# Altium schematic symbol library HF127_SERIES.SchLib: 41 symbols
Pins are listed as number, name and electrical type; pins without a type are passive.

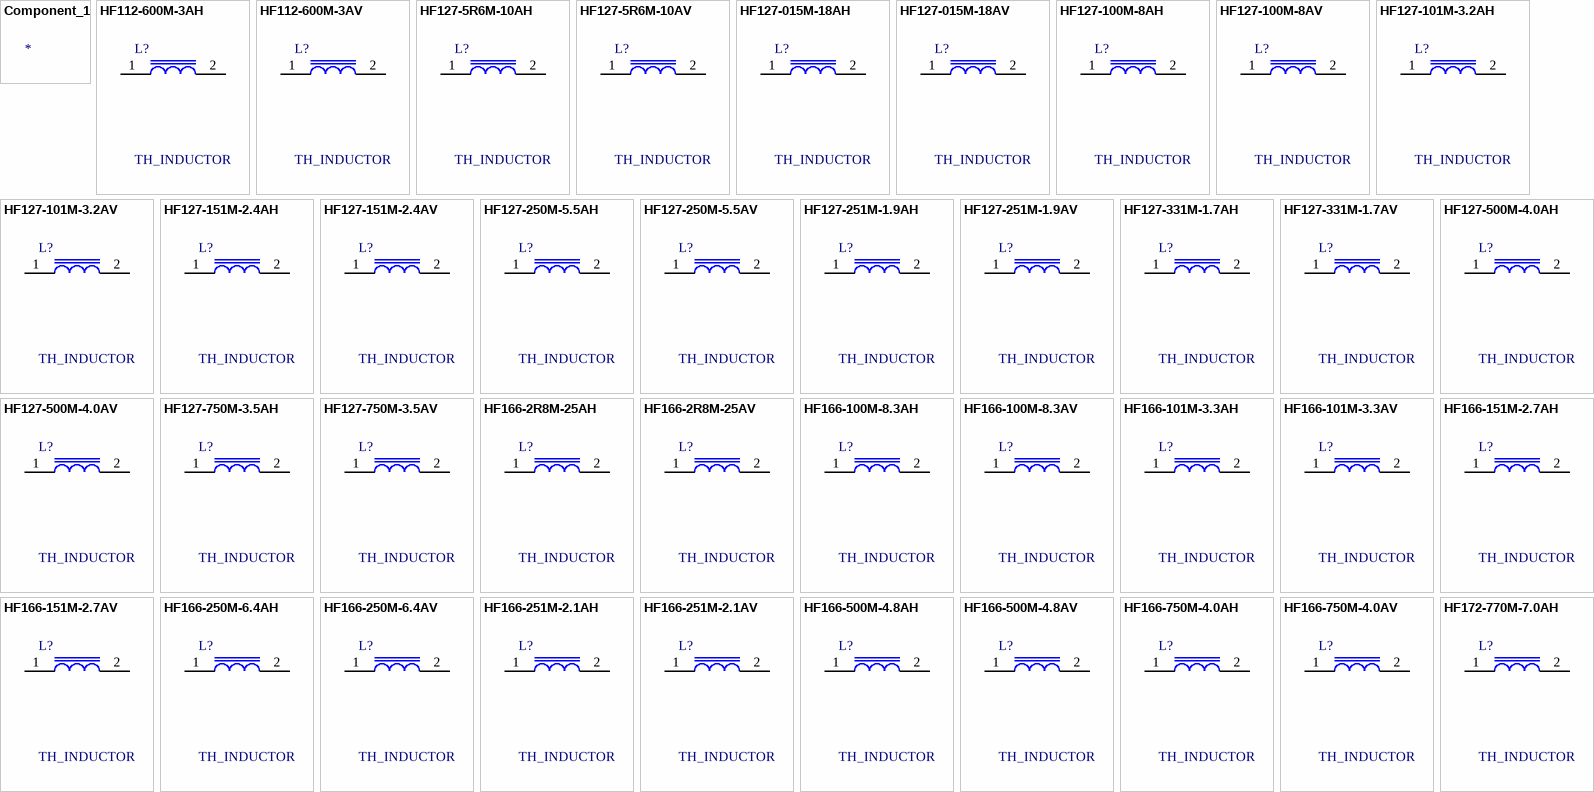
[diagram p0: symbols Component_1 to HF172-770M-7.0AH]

## Component_1
designator *  (value not drawn)

## HF112-600M-3AH
designator L?, comment TH_INDUCTOR
POWER INDUCTOR 3 A, 60 uH, 30 mOhms, OD 13.46 mm, HT 7.62 mm; Manufacturer #1: CWS; Sim.Analog.Prefix: L; Sim.Analog.Order: Model$; Current: 3.0 A; Inductance: 60.00 uH
footprint HF112-600M-3AH
pins: 1, 2

## HF112-600M-3AV
designator L?, comment TH_INDUCTOR
POWER INDUCTOR 3 A, 60 uH, 30 mOhms, OD 13.46 mm, HT 7.62 mm; Manufacturer #1: CWS; Sim.Analog.Prefix: L; Sim.Analog.Order: Model$; Current: 3.0 A; Inductance: 60.00 uH
footprint HF112-600M-3AV
pins: 1, 2

## HF127-5R6M-10AH
designator L?, comment TH_INDUCTOR
POWER INDUCTOR 10 A, 5.6 uH, 4 mOhms, OD 18.49 mm, HT 9.4 mm; Manufacturer #1: CWS; Sim.Analog.Prefix: L; Sim.Analog.Order: Model$; Current: 10.0 A; DCR: 4 mOhms; Inductance: 5.60 uH
footprint HF127-5R6M-10AH
pins: 1, 2

## HF127-5R6M-10AV
designator L?, comment TH_INDUCTOR
POWER INDUCTOR 10 A, 5.6 uH, 4 mOhms, OD 18.49 mm, HT 9.4 mm; Manufacturer #1: CWS; Sim.Analog.Prefix: L; Sim.Analog.Order: Model$; Current: 10.0 A; DCR: 4 mOhms; Inductance: 5.60 uH
footprint HF127-5R6M-10AV
pins: 1, 2

## HF127-015M-18AH
designator L?, comment TH_INDUCTOR
POWER INDUCTOR 18 A, 1.5 uH, 2 mOhms, OD 18.8 mm, HT 9.65 mm; Manufacturer #1: CWS; Sim.Analog.Prefix: L; Sim.Analog.Order: Model$; OD: 18.8 mm; Current: 18.0 A; DCR: 2 mOhms; Inductance: 1.50 uH
footprint HF127-015M-18AH
pins: 1, 2

## HF127-015M-18AV
designator L?, comment TH_INDUCTOR
POWER INDUCTOR 18 A, 1.5 uH, 2 mOhms, OD 18.8 mm, HT 9.65 mm; Manufacturer #1: CWS; Sim.Analog.Prefix: L; Sim.Analog.Order: Model$; OD: 18.8 mm; Current: 18.0 A; DCR: 2 mOhms; Inductance: 1.50 uH
footprint HF127-015M-18AV
pins: 1, 2

## HF127-100M-8AH
designator L?, comment TH_INDUCTOR
POWER INDUCTOR 8 A, 10 uH, 10 mOhms, OD 15.88 mm, HT 7.62 mm; Manufacturer #1: CWS; Sim.Analog.Prefix: L; Sim.Analog.Order: Model$; Current: 8.0 A; Inductance: 10.00 uH
footprint HF127-100M-8AH
pins: 1, 2

## HF127-100M-8AV
designator L?, comment TH_INDUCTOR
POWER INDUCTOR 8 A, 10 uH, 10 mOhms, OD 15.88 mm, HT 7.62 mm; Manufacturer #1: CWS; Sim.Analog.Prefix: L; Sim.Analog.Order: Model$; Current: 8.0 A; Inductance: 10.00 uH
footprint HF127-100M-8AV
pins: 1, 2

## HF127-101M-3.2AH
designator L?, comment TH_INDUCTOR
POWER INDUCTOR 3.2 A, 100 uH, 55 mOhms, OD 15.88 mm, HT 7.62 mm; Manufacturer #1: CWS; Sim.Analog.Prefix: L; Sim.Analog.Order: Model$; Current: 3.2 A; Inductance: 100.00 uH
footprint HF127-101M-3.2AV
pins: 1, 2

## HF127-101M-3.2AV
designator L?, comment TH_INDUCTOR
POWER INDUCTOR 3.2 A, 100 uH, 55 mOhms, OD 15.88 mm, HT 7.62 mm; Manufacturer #1: CWS; Sim.Analog.Prefix: L; Sim.Analog.Order: Model$; Current: 3.2 A; Inductance: 100.00 uH
footprint HF127-101M-3.2AV
pins: 1, 2

## HF127-151M-2.4AH
designator L?, comment TH_INDUCTOR
POWER INDUCTOR 2.4 A, 150 uH, 100 mOhms, OD 15.88 mm, HT 7.62 mm; Manufacturer #1: CWS; Sim.Analog.Prefix: L; Sim.Analog.Order: Model$; Current: 2.4 A; Inductance: 150.00 uH
footprint HF127-151M-2.4AH 
pins: 1, 2

## HF127-151M-2.4AV
designator L?, comment TH_INDUCTOR
POWER INDUCTOR 2.4 A, 150 uH, 100 mOhms, OD 15.88 mm, HT 7.62 mm; Manufacturer #1: CWS; Sim.Analog.Prefix: L; Sim.Analog.Order: Model$; Current: 2.4 A; Inductance: 150.00 uH
footprint HF127-151M-2.4AV
pins: 1, 2

## HF127-250M-5.5AH
designator L?, comment TH_INDUCTOR
POWER INDUCTOR 5.5 A, 25 uH, 20 mOhms, OD 15.88 mm, HT 7.62 mm; Manufacturer #1: CWS; Sim.Analog.Prefix: L; Sim.Analog.Order: Model$; Current: 5.5 A; Inductance: 25.00 uH
footprint HF127-250M-5.5AH
pins: 1, 2

## HF127-250M-5.5AV
designator L?, comment TH_INDUCTOR
POWER INDUCTOR 5.5 A, 25 uH, 20 mOhms, OD 15.88 mm, HT 7.62 mm; Manufacturer #1: CWS; Sim.Analog.Prefix: L; Sim.Analog.Order: Model$; Current: 5.5 A; Inductance: 25.00 uH
footprint HF127-250M-5.5AV
pins: 1, 2

## HF127-251M-1.9AH
designator L?, comment TH_INDUCTOR
POWER INDUCTOR 1.9 A, 250 uH, 160 mOhms, OD 15.88 mm, HT 7.62 mm; Manufacturer #1: CWS; Sim.Analog.Prefix: L; Sim.Analog.Order: Model$; Current: 1.9 A; Inductance: 250.00 uH
footprint HF127-251M-1.9AH 
pins: 1, 2

## HF127-251M-1.9AV
designator L?, comment TH_INDUCTOR
POWER INDUCTOR 1.9 A, 250 uH, 160 mOhms, OD 15.88 mm, HT 7.62 mm; Manufacturer #1: CWS; Sim.Analog.Prefix: L; Sim.Analog.Order: Model$; Current: 1.9 A; Inductance: 250.00 uH
footprint HF127-251M-1.9AV
pins: 1, 2

## HF127-331M-1.7AH
designator L?, comment TH_INDUCTOR
POWER INDUCTOR 1.7 A, 330 uH, 190 mOhms, OD 15.88 mm, HT 7.62 mm; Manufacturer #1: CWS; Sim.Analog.Prefix: L; Sim.Analog.Order: Model$; Current: 1.7 A; Inductance: 330.00 uH
footprint HF127-331M-1.7AH
pins: 1, 2

## HF127-331M-1.7AV
designator L?, comment TH_INDUCTOR
POWER INDUCTOR 1.7 A, 330 uH, 190 mOhms, OD 15.88 mm, HT 7.62 mm; Manufacturer #1: CWS; Sim.Analog.Prefix: L; Sim.Analog.Order: Model$; Current: 1.7 A; Inductance: 330.00 uH
footprint HF127-331M-1.7AV
pins: 1, 2

## HF127-500M-4.0AH
designator L?, comment TH_INDUCTOR
POWER INDUCTOR 4 A, 50 uH, 35 mOhms, OD 15.88 mm, HT 7.62 mm; Manufacturer #1: CWS; Sim.Analog.Prefix: L; Sim.Analog.Order: Model$; Current: 4.0 A; Inductance: 50.00 uH
footprint HF127-500M-4.0AH
pins: 1, 2

## HF127-500M-4.0AV
designator L?, comment TH_INDUCTOR
POWER INDUCTOR 4 A, 50 uH, 35 mOhms, OD 15.88 mm, HT 7.62 mm; Manufacturer #1: CWS; Sim.Analog.Prefix: L; Sim.Analog.Order: Model$; Current: 4.0 A; Inductance: 50.00 uH
footprint HF127-500M-4.0AV
pins: 1, 2

## HF127-750M-3.5AH
designator L?, comment TH_INDUCTOR
POWER INDUCTOR 3.5 A, 75 uH, 45 mOhms, OD 15.88 mm, HT 7.62 mm; Manufacturer #1: CWS; Sim.Analog.Prefix: L; Sim.Analog.Order: Model$; Current: 3.5 A; Inductance: 75.00 uH
footprint HF127-750M-3.5AH
pins: 1, 2

## HF127-750M-3.5AV
designator L?, comment TH_INDUCTOR
POWER INDUCTOR 3.5 A, 75 uH, 45 mOhms, OD 15.88 mm, HT 7.62 mm; Manufacturer #1: CWS; Sim.Analog.Prefix: L; Sim.Analog.Order: Model$; Current: 3.5 A; Inductance: 75.00 uH
footprint HF127-750M-3.5AV
pins: 1, 2

## HF166-2R8M-25AH
designator L?, comment TH_INDUCTOR
POWER INDUCTOR 25 A, 2.8 uH, 2 mOhms, OD 23.88 mm, HT 13.46 mm; Manufacturer #1: CWS; Sim.Analog.Prefix: L; Sim.Analog.Order: Model$; Current: 25.0 A; DCR: 2 mOhms; Inductance: 2.80 uH
footprint HF166-2R8M-25AH
pins: 1, 2

## HF166-2R8M-25AV
designator L?, comment TH_INDUCTOR
POWER INDUCTOR 25 A, 2.8 uH, 2 mOhms, OD 23.88 mm, HT 13.46 mm; Manufacturer #1: CWS; Sim.Analog.Prefix: L; Sim.Analog.Order: Model$; Current: 25.0 A; DCR: 2 mOhms; Inductance: 2.80 uH
footprint HF166-2R8M-25AV
pins: 1, 2

## HF166-100M-8.3AH
designator L?, comment TH_INDUCTOR
POWER INDUCTOR 8.3 A, 10 uH, 10 mOhms, OD 21.59 mm, HT 10.16 mm; Manufacturer #1: CWS; Sim.Analog.Prefix: L; Sim.Analog.Order: Model$; Current: 8.3 A; Inductance: 10.00 uH
footprint HF166-100M-8.3AH
pins: 1, 2

## HF166-100M-8.3AV
designator L?, comment TH_INDUCTOR
POWER INDUCTOR 8.3 A, 10 uH, 10 mOhms, OD 21.59 mm, HT 10.16 mm; Manufacturer #1: CWS; Sim.Analog.Prefix: L; Sim.Analog.Order: Model$; Current: 8.3 A; Inductance: 10.00 uH
footprint HF166-100M-8.3AV
pins: 1, 2

## HF166-101M-3.3AH
designator L?, comment TH_INDUCTOR
POWER INDUCTOR 3.3 A, 100 uH, 65 mOhms, OD 20.83 mm, HT 10.16 mm; Manufacturer #1: CWS; Sim.Analog.Prefix: L; Sim.Analog.Order: Model$; Current: 3.3 A; Inductance: 100.00 uH
footprint HF166-101M-3.3AH
pins: 1, 2

## HF166-101M-3.3AV
designator L?, comment TH_INDUCTOR
POWER INDUCTOR 3.3 A, 100 uH, 65 mOhms, OD 20.83 mm, HT 10.16 mm; Manufacturer #1: CWS; Sim.Analog.Prefix: L; Sim.Analog.Order: Model$; Current: 3.3 A; Inductance: 100.00 uH
footprint HF166-101M-3.3AV 
pins: 1, 2

## HF166-151M-2.7AH
designator L?, comment TH_INDUCTOR
POWER INDUCTOR 2.7 A, 150 uH, 95 mOhms, OD 20.83 mm, HT 10.16 mm; Manufacturer #1: CWS; Sim.Analog.Prefix: L; Sim.Analog.Order: Model$; Current: 2.7 A; Inductance: 150.00 uH
footprint HF166-151M-2.7AH
pins: 1, 2

## HF166-151M-2.7AV
designator L?, comment TH_INDUCTOR
POWER INDUCTOR 2.7 A, 150 uH, 95 mOhms, OD 20.83 mm, HT 10.16 mm; Manufacturer #1: CWS; Sim.Analog.Prefix: L; Sim.Analog.Order: Model$; Current: 2.7 A; Inductance: 150.00 uH
footprint HF166-151M-2.7AV
pins: 1, 2

## HF166-250M-6.4AH
designator L?, comment TH_INDUCTOR
POWER INDUCTOR 6.4 A, 25 uH, 17 mOhms, OD 20.83 mm, HT 10.16 mm; Manufacturer #1: CWS; Sim.Analog.Prefix: L; Sim.Analog.Order: Model$; Current: 6.4 A; Inductance: 25.00 uH
footprint HF166-250M-6.4AH
pins: 1, 2

## HF166-250M-6.4AV
designator L?, comment TH_INDUCTOR
POWER INDUCTOR 6.4 A, 25 uH, 17 mOhms, OD 20.83 mm, HT 10.16 mm; Manufacturer #1: CWS; Sim.Analog.Prefix: L; Sim.Analog.Order: Model$; Current: 6.4 A; Inductance: 25.00 uH
footprint HF166-250M-6.4AV
pins: 1, 2

## HF166-251M-2.1AH
designator L?, comment TH_INDUCTOR
POWER INDUCTOR 2.1 A, 250 uH, 160 mOhms, OD 20.83 mm, HT 10.16 mm; Manufacturer #1: CWS; Sim.Analog.Prefix: L; Sim.Analog.Order: Model$; Current: 2.1 A; Inductance: 250.00 uH
footprint HF166-251M-2.1AH
pins: 1, 2

## HF166-251M-2.1AV
designator L?, comment TH_INDUCTOR
POWER INDUCTOR 2.1 A, 250 uH, 160 mOhms, OD 20.83 mm, HT 10.16 mm; Manufacturer #1: CWS; Sim.Analog.Prefix: L; Sim.Analog.Order: Model$; Current: 2.1 A; Inductance: 250.00 uH
footprint HF166-251M-2.1AV
pins: 1, 2

## HF166-500M-4.8AH
designator L?, comment TH_INDUCTOR
POWER INDUCTOR 4.8 A, 50 uH, 30 mOhms, OD 20.83 mm, HT 10.16 mm; Manufacturer #1: CWS; Sim.Analog.Prefix: L; Sim.Analog.Order: Model$; Current: 4.8 A; Inductance: 50.00 uH
footprint HF166-500M-4.8AH
pins: 1, 2

## HF166-500M-4.8AV
designator L?, comment TH_INDUCTOR
POWER INDUCTOR 4.8 A, 50 uH, 30 mOhms, OD 20.83 mm, HT 10.16 mm; Manufacturer #1: CWS; Sim.Analog.Prefix: L; Sim.Analog.Order: Model$; Current: 4.8 A; Inductance: 50.00 uH
footprint HF166-500M-4.8AV
pins: 1, 2

## HF166-750M-4.0AH
designator L?, comment TH_INDUCTOR
POWER INDUCTOR 4 A, 75 uH, 45 mOhms, OD 20.83 mm, HT 10.16 mm; Manufacturer #1: CWS; Sim.Analog.Prefix: L; Sim.Analog.Order: Model$; Current: 4.0 A; Inductance: 75.00 uH
footprint HF166-750M-4.0AH
pins: 1, 2

## HF166-750M-4.0AV
designator L?, comment TH_INDUCTOR
POWER INDUCTOR 4 A, 75 uH, 45 mOhms, OD 20.83 mm, HT 10.16 mm; Manufacturer #1: CWS; Sim.Analog.Prefix: L; Sim.Analog.Order: Model$; Current: 4.0 A; Inductance: 75.00 uH
footprint HF166-750M-4.0AV
pins: 1, 2

## HF172-770M-7.0AH
designator L?, comment TH_INDUCTOR
POWER INDUCTOR 7 A, 77 uH, 14 mOhms, OD 24.13 mm, HT 11.94 mm; Manufacturer #1: CWS; Sim.Analog.Prefix: L; Sim.Analog.Order: Model$; Current: 7.0 A; Inductance: 77.00 uH
footprint HF172-770M-7.0AH
pins: 1, 2

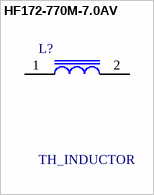
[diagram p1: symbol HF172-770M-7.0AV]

## HF172-770M-7.0AV
designator L?, comment TH_INDUCTOR
POWER INDUCTOR 7 A, 77 uH, 14 mOhms, OD 24 mm, HT 11.94 mm; Manufacturer #1: CWS; Sim.Analog.Prefix: L; Sim.Analog.Order: Model$; OD: 24 mm; Current: 7.0 A; Inductance: 77.00 uH
footprint HF172-770M-7.0AV
pins: 1, 2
